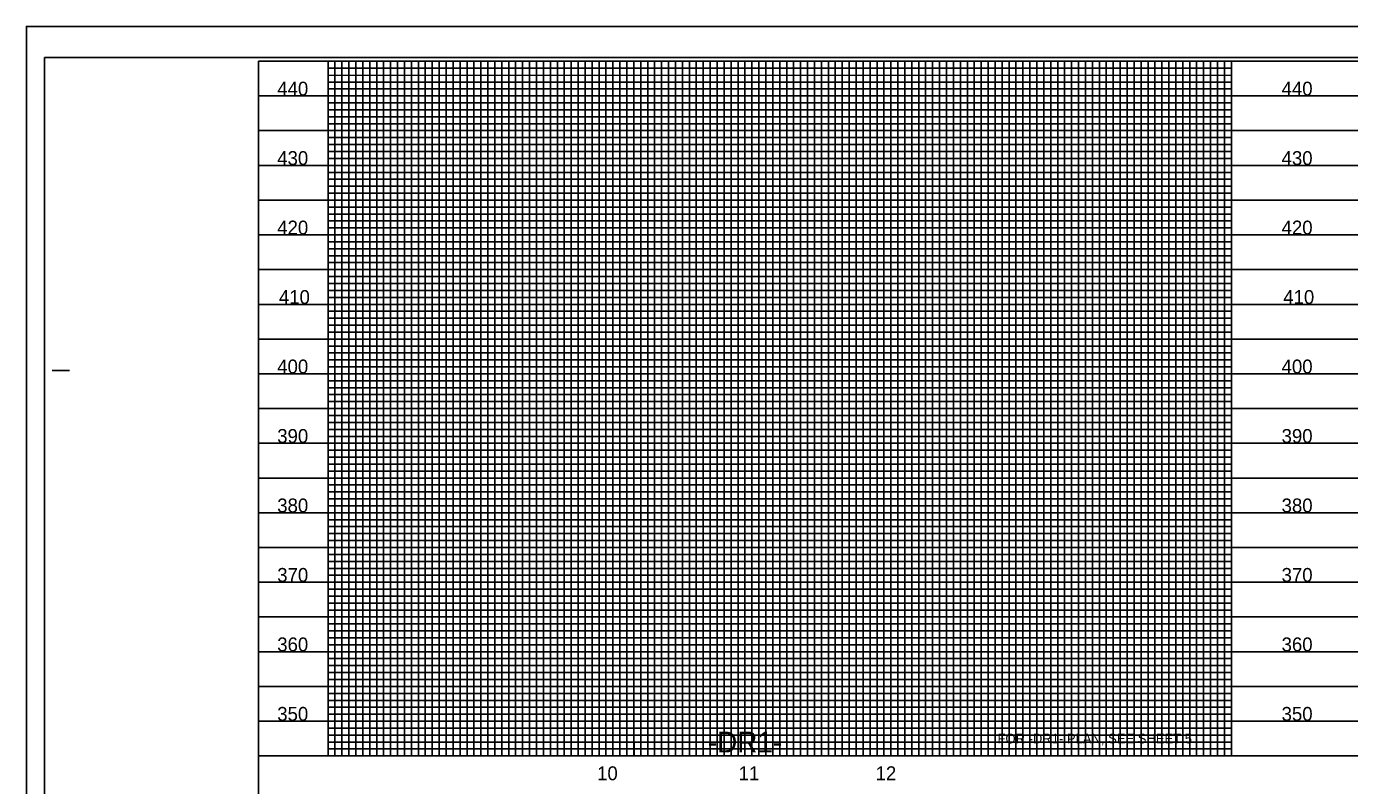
# Model space of a CAD drawing. Extents: x 1629787 to 1631995, y 1166253 to 1167353.
# Drawn here: x 1629787 to 1630739, y 1166807 to 1167353 of the extents above; entities that cross this region are included whole.
import ezdxf

# ---------------------------------------------------------------- set-up
doc = ezdxf.new("R2010")
doc.units = 0
for name, color, linetype in [('Exist Vertical Profile Horizontal Axis Label Major', 7, 'Continuous'), ('Exist Vertical Profile Vertical Axis Label', 7, 'Continuous'), ('Prop Grid Mask', 7, 'Continuous'), ('Sheet Data Field CELL', 7, 'Continuous'), ('Sheet Layout Profile Border Port 1', 7, 'Continuous'), ('Sheet Plot Border Inside CELL', 7, 'Continuous'), ('Sheet Plot Border Outside CELL', 7, 'Continuous'), ('Sheet Profile CELL', 7, 'Continuous'), ('Sheet Profile Grid Major CELL', 7, 'Continuous'), ('Sheet Profile Grid Middle CELL', 7, 'Continuous'), ('Sheet Profile Grid Minor CELL', 7, 'Continuous')]:
    doc.layers.add(name, color=color, linetype=linetype)

msp = doc.modelspace()

# ---------------------------------------------------------------- linework, layer by layer
at = {"layer": 'Prop Grid Mask'}
for points in [[(1630224.31, 1166848.4), (1630384.31, 1166848.4), (1630384.31, 1166828.4), (1630224.31, 1166828.4)], [(1630454.31, 1166853.4), (1630654.31, 1166853.4), (1630654.31, 1166828.4), (1630454.31, 1166828.4)]]:
    msp.add_lwpolyline(points, close=True, dxfattribs=at)
at = {"layer": 'Sheet Data Field CELL'}
for points in [[(1630224.31, 1166828.4), (1630384.31, 1166828.4), (1630384.31, 1166848.4), (1630224.31, 1166848.4)], [(1630654.31, 1166828.4), (1630454.31, 1166828.4), (1630454.31, 1166853.4), (1630654.31, 1166853.4)]]:
    msp.add_lwpolyline(points, close=True, dxfattribs=at)
at = {"layer": 'Sheet Layout Profile Border Port 1'}
msp.add_lwpolyline([(1630004.31, 1167328.4), (1630654.31, 1167328.4), (1630654.31, 1166828.4), (1630384.31, 1166828.4), (1630384.31, 1166848.4), (1630224.31, 1166848.4), (1630224.46, 1166828.4), (1630004.31, 1166828.4)], close=True, dxfattribs=at)
at = {"layer": 'Sheet Plot Border Inside CELL'}
msp.add_lwpolyline([(1629800.31, 1166275.85), (1631466.81, 1166275.85), (1631466.81, 1167330.95), (1629800.31, 1167330.95)], close=True, dxfattribs=at)
at = {"layer": 'Sheet Plot Border Outside CELL'}
msp.add_lwpolyline([(1629787.31, 1166253.4), (1631471.31, 1166253.4), (1631471.31, 1167353.4), (1629787.31, 1167353.4)], close=True, dxfattribs=at)
at = {"layer": 'Sheet Profile CELL'}
for p, q in [((1629805.81, 1167105.9), (1629818.31, 1167105.9)), ((1631454.31, 1166828.4), (1629954.31, 1166828.4))]:
    msp.add_line(p, q, dxfattribs=at)
msp.add_lwpolyline([(1631454.31, 1167328.4), (1629954.31, 1167328.4), (1629954.31, 1166278.4), (1631454.31, 1166278.4)], close=True, dxfattribs=at)
at = {"layer": 'Sheet Profile Grid Major CELL'}
for p, q in [((1630004.31, 1167328.4), (1630004.31, 1166828.4)), ((1630054.31, 1166828.4), (1630054.31, 1167328.4)), ((1630054.31, 1167328.4), (1630104.31, 1167328.4)), ((1630104.31, 1167328.4), (1630104.31, 1166828.4)), ((1630154.31, 1166828.4), (1630154.31, 1167328.4)), ((1630154.31, 1167328.4), (1630204.31, 1167328.4)), ((1630204.31, 1167328.4), (1630204.31, 1166828.4)), ((1630254.31, 1166828.4), (1630254.31, 1167328.4)), ((1630254.31, 1167328.4), (1630304.31, 1167328.4)), ((1630304.31, 1167328.4), (1630304.31, 1166828.4)), ((1630354.31, 1166828.4), (1630354.31, 1167328.4)), ((1630354.31, 1167328.4), (1630404.31, 1167328.4)), ((1630404.31, 1167328.4), (1630404.31, 1166828.4)), ((1630454.31, 1166828.4), (1630454.31, 1167328.4)), ((1630454.31, 1167328.4), (1630504.31, 1167328.4)), ((1630504.31, 1167328.4), (1630504.31, 1166828.4)), ((1630554.31, 1166828.4), (1630554.31, 1167328.4)), ((1630554.31, 1167328.4), (1630604.31, 1167328.4)), ((1630604.31, 1167328.4), (1630604.31, 1166828.4)), ((1630654.31, 1166828.4), (1630654.31, 1167328.4)), ((1630654.31, 1167328.4), (1630704.31, 1167328.4)), ((1630004.31, 1166828.4), (1630054.31, 1166828.4)), ((1630104.31, 1166828.4), (1630154.31, 1166828.4)), ((1630204.31, 1166828.4), (1630254.31, 1166828.4)), ((1630304.31, 1166828.4), (1630354.31, 1166828.4)), ((1630404.31, 1166828.4), (1630454.31, 1166828.4)), ((1630504.31, 1166828.4), (1630554.31, 1166828.4)), ((1630604.31, 1166828.4), (1630634.31, 1166828.4))]:
    msp.add_line(p, q, dxfattribs=at)
for points in [[(1629954.31, 1167303.4), (1631054.21, 1167303.4)], [(1629954.31, 1167253.4), (1631254.26, 1167253.4)], [(1631254.26, 1167203.4), (1629954.31, 1167203.4), (1629954.31, 1167153.4), (1631454.31, 1167153.4)], [(1631454.31, 1167103.4), (1629954.31, 1167103.4), (1629954.31, 1167053.4), (1631454.31, 1167053.4)], [(1631454.31, 1167003.4), (1629954.31, 1167003.4), (1629954.31, 1166953.4), (1631454.31, 1166953.4)], [(1631454.31, 1166903.4), (1629954.31, 1166903.4), (1629954.31, 1166903.4), (1629954.31, 1166853.4), (1631454.31, 1166853.4)]]:
    msp.add_lwpolyline(points, dxfattribs=at)
at = {"layer": 'Sheet Profile Grid Middle CELL'}
msp.add_line((1629954.31, 1167328.4), (1631054.21, 1167328.4), dxfattribs=at)
for points in [[(1630029.31, 1167328.4), (1630029.31, 1166828.4), (1630079.31, 1166828.4), (1630079.31, 1167328.4), (1630129.31, 1167328.4), (1630129.31, 1166828.4), (1630179.31, 1166828.4), (1630179.31, 1167328.4), (1630229.31, 1167328.4), (1630229.31, 1166828.4), (1630279.31, 1166828.4), (1630279.31, 1167328.4), (1630329.31, 1167328.4), (1630329.31, 1166828.4), (1630379.31, 1166828.4), (1630379.31, 1167328.4), (1630429.31, 1167328.4), (1630429.31, 1166828.4), (1630479.31, 1166828.4), (1630479.31, 1167328.4), (1630529.31, 1167328.4), (1630529.31, 1166828.4), (1630579.31, 1166828.4), (1630579.31, 1166828.4), (1630579.31, 1167328.4), (1630629.31, 1167328.4), (1630629.31, 1166828.4)], [(1631254.26, 1167278.4), (1629954.31, 1167278.4), (1629954.31, 1167228.4), (1631254.26, 1167228.4)], [(1631254.26, 1167178.4), (1629954.31, 1167178.4), (1629954.31, 1167128.4), (1631454.31, 1167128.4)], [(1631454.31, 1167078.4), (1629954.31, 1167078.4), (1629954.31, 1167028.4), (1631454.31, 1167028.4)], [(1631454.31, 1166978.4), (1629954.31, 1166978.4), (1629954.31, 1166928.4), (1631454.31, 1166928.4)], [(1631454.31, 1166878.4), (1629954.31, 1166878.4)]]:
    msp.add_lwpolyline(points, dxfattribs=at)
at = {"layer": 'Sheet Profile Grid Minor CELL'}
for p, q in [((1630004.31, 1167323.4), (1630654.31, 1167323.4)), ((1630534.31, 1167328.4), (1630534.31, 1166828.4)), ((1630539.31, 1166828.4), (1630539.31, 1167328.4)), ((1630539.31, 1167328.4), (1630544.31, 1167328.4)), ((1630544.31, 1167328.4), (1630544.31, 1166828.4)), ((1630549.31, 1166828.4), (1630549.31, 1167328.4)), ((1630549.31, 1167328.4), (1630559.31, 1167328.4)), ((1630559.31, 1167328.4), (1630559.31, 1166828.4)), ((1630564.31, 1166828.4), (1630564.31, 1167328.4)), ((1630564.31, 1167328.4), (1630569.31, 1167328.4)), ((1630569.31, 1167328.4), (1630569.31, 1166828.4)), ((1630574.31, 1166828.4), (1630574.31, 1167328.4)), ((1630574.31, 1167328.4), (1630584.31, 1167328.4)), ((1630584.31, 1167328.4), (1630584.31, 1166828.4)), ((1630589.31, 1166828.4), (1630589.31, 1167328.4)), ((1630589.31, 1167328.4), (1630594.31, 1167328.4)), ((1630594.31, 1167328.4), (1630594.31, 1166828.4)), ((1630599.31, 1166828.4), (1630599.31, 1167328.4)), ((1630599.31, 1167328.4), (1630609.31, 1167328.4)), ((1630609.31, 1167328.4), (1630609.31, 1166828.4)), ((1630614.31, 1166828.4), (1630614.31, 1167328.4)), ((1630614.31, 1167328.4), (1630619.31, 1167328.4)), ((1630619.31, 1167328.4), (1630619.31, 1166828.4)), ((1630624.31, 1166828.4), (1630624.31, 1167328.4)), ((1630624.31, 1167328.4), (1630634.31, 1167328.4)), ((1630634.31, 1167328.4), (1630634.31, 1166828.4)), ((1630639.31, 1166828.4), (1630639.31, 1167328.4)), ((1630639.31, 1167328.4), (1630644.31, 1167328.4)), ((1630644.31, 1167328.4), (1630644.31, 1166828.4)), ((1630649.31, 1166828.4), (1630649.31, 1167328.4)), ((1630649.31, 1167328.4), (1630659.31, 1167328.4)), ((1630004.31, 1167318.4), (1630004.31, 1167318.4)), ((1630654.31, 1167318.23), (1630004.31, 1167318.05)), ((1630004.31, 1167313.4), (1630654.31, 1167313.4)), ((1630654.31, 1167193.4), (1630004.31, 1167193.4)), ((1630654.31, 1167188.4), (1630004.31, 1167188.4)), ((1630654.31, 1167183.4), (1630004.31, 1167183.4)), ((1630004.31, 1167173.4), (1630654.31, 1167173.4)), ((1630654.31, 1167168.4), (1630004.31, 1167168.4)), ((1630004.31, 1167163.4), (1630654.31, 1167163.4)), ((1630654.31, 1167143.4), (1630004.31, 1167143.4)), ((1630004.31, 1167138.4), (1630654.31, 1167138.4)), ((1630654.31, 1167118.4), (1630004.31, 1167118.4)), ((1630004.31, 1167113.4), (1630654.31, 1167113.4)), ((1630654.31, 1167093.4), (1630004.31, 1167093.4)), ((1630004.31, 1167088.4), (1630654.31, 1167088.4)), ((1630654.31, 1167083.4), (1630004.31, 1167083.4)), ((1630004.31, 1167073.4), (1630654.31, 1167073.4)), ((1630654.31, 1167068.4), (1630004.31, 1167068.4)), ((1630004.31, 1167063.4), (1630654.31, 1167063.4)), ((1630654.31, 1167058.4), (1630004.31, 1167058.4)), ((1630004.31, 1167048.4), (1630654.31, 1167048.4)), ((1630654.31, 1167043.4), (1630004.31, 1167043.4)), ((1630004.31, 1167038.4), (1630654.31, 1167038.4)), ((1630654.31, 1167033.4), (1630004.31, 1167033.4)), ((1630004.31, 1167023.4), (1630654.31, 1167023.4)), ((1630654.31, 1167018.4), (1630004.31, 1167018.4)), ((1630004.31, 1167013.4), (1630654.31, 1167013.4)), ((1630654.31, 1167008.4), (1630004.31, 1167008.4)), ((1630004.31, 1166998.4), (1630654.31, 1166998.4)), ((1630654.31, 1166993.4), (1630004.31, 1166993.4)), ((1630004.31, 1166988.4), (1630654.31, 1166988.4)), ((1630654.31, 1166983.4), (1630004.31, 1166983.4)), ((1630004.31, 1166973.4), (1630654.31, 1166973.4)), ((1630654.31, 1166968.4), (1630004.31, 1166968.4)), ((1630004.31, 1166963.4), (1630654.31, 1166963.4)), ((1630654.31, 1166958.4), (1630004.31, 1166958.4)), ((1630004.31, 1166948.4), (1630654.31, 1166948.4)), ((1630654.31, 1166943.4), (1630004.31, 1166943.4)), ((1630654.31, 1166938.4), (1630004.31, 1166938.4)), ((1630654.31, 1166933.4), (1630004.31, 1166933.4)), ((1630004.31, 1166923.4), (1630654.31, 1166923.4)), ((1630654.31, 1166918.4), (1630004.31, 1166918.4)), ((1630004.31, 1166913.4), (1630654.31, 1166913.4)), ((1630654.31, 1166908.4), (1630004.31, 1166908.4)), ((1630004.31, 1166898.4), (1630654.31, 1166898.4)), ((1630654.31, 1166893.4), (1630004.31, 1166893.4)), ((1630004.31, 1166888.4), (1630654.31, 1166888.4)), ((1630654.31, 1166883.4), (1630004.31, 1166883.4)), ((1630004.31, 1166873.4), (1630654.31, 1166873.4)), ((1630654.31, 1166868.4), (1630004.31, 1166868.4)), ((1630004.31, 1166863.4), (1630654.31, 1166863.4)), ((1630654.31, 1166858.4), (1630004.31, 1166858.4)), ((1630004.31, 1166848.4), (1630654.31, 1166848.4)), ((1630624.31, 1166843.4), (1630004.31, 1166843.4)), ((1630004.31, 1166838.4), (1630624.31, 1166838.4)), ((1630654.31, 1166843.4), (1630624.31, 1166843.4)), ((1630624.31, 1166838.4), (1630654.31, 1166838.4)), ((1630534.31, 1166828.4), (1630539.31, 1166828.4)), ((1630544.31, 1166828.4), (1630549.31, 1166828.4)), ((1630559.31, 1166828.4), (1630564.31, 1166828.4)), ((1630569.31, 1166828.4), (1630574.31, 1166828.4)), ((1630584.31, 1166828.4), (1630589.31, 1166828.4)), ((1630594.31, 1166828.4), (1630599.31, 1166828.4)), ((1630609.31, 1166828.4), (1630614.31, 1166828.4)), ((1630619.31, 1166828.4), (1630624.31, 1166828.4)), ((1630634.31, 1166828.4), (1630639.31, 1166828.4)), ((1630644.31, 1166828.4), (1630649.31, 1166828.4))]:
    msp.add_line(p, q, dxfattribs=at)
for points in [[(1630009.31, 1167328.4), (1630009.31, 1166828.4), (1630014.31, 1166828.4), (1630014.31, 1167328.4), (1630019.31, 1167328.4), (1630019.31, 1166828.4), (1630024.31, 1166828.4), (1630024.31, 1167328.4), (1630034.31, 1167328.4), (1630034.31, 1166828.4), (1630039.31, 1166828.4), (1630039.31, 1167328.4), (1630044.31, 1167328.4), (1630044.31, 1166828.4), (1630049.31, 1166828.4), (1630059.31, 1166828.4), (1630064.31, 1166828.4), (1630064.31, 1167328.4), (1630069.31, 1167328.4), (1630069.31, 1166828.4), (1630074.31, 1166828.4), (1630074.31, 1167328.4), (1630084.31, 1167328.4), (1630084.31, 1166828.4), (1630089.31, 1166828.4), (1630089.31, 1167328.4), (1630094.31, 1167328.4), (1630094.31, 1166828.4), (1630099.31, 1166828.4), (1630099.31, 1167328.4), (1630109.31, 1167328.4), (1630109.31, 1166828.4), (1630114.31, 1166828.4), (1630114.31, 1167328.4), (1630119.31, 1167328.4), (1630119.31, 1166828.4), (1630124.31, 1166828.4), (1630124.31, 1167328.4), (1630134.31, 1167328.4), (1630134.31, 1166828.4), (1630139.31, 1166828.4), (1630139.31, 1167328.4), (1630144.31, 1167328.4), (1630144.31, 1166828.4), (1630149.31, 1166828.4), (1630149.31, 1167328.4), (1630159.31, 1167328.4), (1630159.31, 1166828.4), (1630164.31, 1166828.4), (1630164.31, 1167328.4), (1630169.31, 1167328.4), (1630169.31, 1166828.4), (1630174.31, 1166828.4), (1630174.31, 1167328.4), (1630184.31, 1167328.4), (1630184.31, 1166828.4), (1630189.31, 1166828.4), (1630189.31, 1167328.4), (1630194.31, 1167328.4), (1630194.31, 1166828.4), (1630199.31, 1166828.4), (1630199.31, 1167328.4), (1630209.31, 1167328.4), (1630209.31, 1166828.4), (1630214.31, 1166828.4), (1630214.31, 1167328.4), (1630219.31, 1167328.4), (1630219.31, 1166828.4)], [(1630049.31, 1166828.4), (1630049.31, 1167328.4), (1630059.31, 1167328.4), (1630059.31, 1166828.4)], [(1630219.31, 1166828.4), (1630224.31, 1166828.4), (1630224.31, 1167328.4), (1630234.31, 1167328.4), (1630234.31, 1166828.4), (1630239.31, 1166828.4), (1630239.31, 1167328.4), (1630244.31, 1167328.4), (1630244.31, 1166828.4), (1630249.31, 1166828.4), (1630249.31, 1167328.4), (1630259.31, 1167328.4), (1630259.31, 1166828.4), (1630264.31, 1166828.4), (1630264.31, 1167328.4), (1630269.31, 1167328.4), (1630269.31, 1166828.4), (1630274.31, 1166828.4), (1630274.31, 1167328.4), (1630284.31, 1167328.4), (1630284.31, 1166828.4), (1630289.31, 1166828.4), (1630289.31, 1167328.4), (1630294.31, 1167328.4), (1630294.31, 1166828.4), (1630299.31, 1166828.4), (1630299.31, 1167328.4), (1630309.31, 1167328.4), (1630309.31, 1166828.4), (1630314.31, 1166828.4), (1630314.31, 1167328.4), (1630319.31, 1167328.4), (1630319.31, 1166828.4), (1630324.31, 1166828.4), (1630324.31, 1167328.4), (1630334.31, 1167328.4), (1630334.31, 1166828.4), (1630339.31, 1166828.4), (1630339.31, 1167328.4), (1630344.31, 1167328.4), (1630344.31, 1166828.4), (1630349.31, 1166828.4), (1630349.31, 1167328.4), (1630359.31, 1167328.4), (1630359.31, 1166828.4), (1630364.31, 1166828.4), (1630364.31, 1167328.4), (1630369.31, 1167328.4), (1630369.31, 1166828.4), (1630374.31, 1166828.4), (1630374.31, 1167328.4), (1630384.31, 1167328.4), (1630384.31, 1166828.4), (1630389.31, 1166828.4), (1630389.31, 1167328.4), (1630394.31, 1167328.4), (1630394.31, 1166828.4), (1630399.31, 1166828.4), (1630399.31, 1167328.4), (1630409.31, 1167328.4), (1630409.31, 1166828.4), (1630414.31, 1166828.4), (1630414.31, 1167328.4), (1630419.31, 1167328.4), (1630419.31, 1166828.4), (1630424.31, 1166828.4), (1630424.31, 1167328.4), (1630434.31, 1167328.4), (1630434.31, 1166828.4), (1630439.31, 1166828.4), (1630439.31, 1167328.4), (1630444.31, 1167328.4), (1630444.31, 1166828.4), (1630449.31, 1166828.4), (1630449.31, 1167328.4), (1630459.31, 1167328.4), (1630459.31, 1166828.4), (1630464.31, 1166828.4), (1630464.31, 1167328.4), (1630469.31, 1167328.4), (1630469.31, 1166828.4), (1630474.31, 1166828.4), (1630474.31, 1167328.4), (1630484.31, 1167328.4), (1630484.31, 1166828.4), (1630489.31, 1166828.4), (1630489.31, 1167328.4), (1630494.31, 1167328.4), (1630494.31, 1166828.4), (1630499.31, 1166828.4), (1630499.31, 1167328.4), (1630509.31, 1167328.4), (1630509.31, 1166828.4), (1630514.31, 1166828.4), (1630514.31, 1167328.4), (1630519.31, 1167328.4), (1630519.31, 1166828.4), (1630524.31, 1166828.4), (1630524.31, 1167328.4), (1630534.31, 1167328.4)], [(1630654.31, 1167308.4), (1630004.31, 1167308.4), (1630004.31, 1167298.4), (1630654.31, 1167298.4)], [(1630654.31, 1167293.4), (1630004.31, 1167293.4), (1630004.31, 1167288.4), (1630654.31, 1167288.4)], [(1630654.31, 1167283.4), (1630004.31, 1167283.4), (1630004.31, 1167273.4), (1630654.31, 1167273.4)], [(1630654.31, 1167268.4), (1630004.31, 1167268.4), (1630004.31, 1167263.4), (1630654.31, 1167263.4)], [(1630654.31, 1167258.4), (1630004.31, 1167258.4), (1630004.31, 1167248.4), (1630654.31, 1167248.4)], [(1630654.31, 1167243.4), (1630004.31, 1167243.4), (1630004.31, 1167238.4), (1630654.31, 1167238.4)], [(1630654.31, 1167233.4), (1630004.31, 1167233.4), (1630004.31, 1167223.4), (1630654.31, 1167223.4)], [(1630654.31, 1167218.3), (1630004.41, 1167218.3), (1630004.41, 1167213.4), (1630654.31, 1167213.4)], [(1630654.31, 1167208.4), (1630004.31, 1167208.4), (1630004.31, 1167198.4), (1630654.31, 1167198.4)], [(1630654.31, 1167158.4), (1630004.31, 1167158.4), (1630004.31, 1167148.4), (1630654.31, 1167148.4)], [(1630654.31, 1167133.4), (1630004.31, 1167133.4), (1630004.31, 1167123.4), (1630654.31, 1167123.4)], [(1630654.31, 1167108.4), (1630004.31, 1167108.4), (1630004.31, 1167098.4), (1630654.31, 1167098.4)], [(1630624.31, 1166833.4), (1630004.31, 1166833.4)], [(1630654.31, 1166833.4), (1630624.31, 1166833.4)]]:
    msp.add_lwpolyline(points, dxfattribs=at)

# ---------------------------------------------------------------- texts
at = {"layer": 'Exist Vertical Profile Horizontal Axis Label Major'}
for s, p in [('10', (1630197.9, 1166810.9)), ('11', (1630299.74, 1166810.9)), ('12', (1630398.29, 1166810.9))]:
    msp.add_text(s, height=10, dxfattribs=at).set_placement(p)
at = {"layer": 'Exist Vertical Profile Vertical Axis Label'}
for s, p in [('440', (1629967.75, 1167303.65)), ('440', (1630690.42, 1167303.65)), ('430', (1629967.75, 1167253.65)), ('430', (1630690.42, 1167253.65)), ('420', (1629967.75, 1167203.65)), ('420', (1630690.42, 1167203.65)), ('410', (1629968.94, 1167153.65)), ('410', (1630691.62, 1167153.65)), ('400', (1629967.75, 1167103.65)), ('400', (1630690.42, 1167103.65)), ('390', (1629967.75, 1167053.65)), ('390', (1630690.42, 1167053.65)), ('380', (1629967.75, 1167003.65)), ('380', (1630690.42, 1167003.65)), ('370', (1629967.75, 1166953.65)), ('370', (1630690.42, 1166953.65)), ('360', (1629967.75, 1166903.65)), ('360', (1630690.42, 1166903.65)), ('350', (1629967.75, 1166853.65)), ('350', (1630690.42, 1166853.65))]:
    msp.add_text(s, height=10, dxfattribs=at).set_placement(p)
at = {"layer": 'Sheet Data Field CELL'}
for s, height, p in [('-DR1-', 15, (1630277.6, 1166830.9)), ('FOR -DR1- PLAN, SEE SHEET 5', 7, (1630486.03, 1166837.4))]:
    msp.add_text(s, height=height, rotation=360, dxfattribs=at).set_placement(p)

doc.saveas('drawing.dxf')
